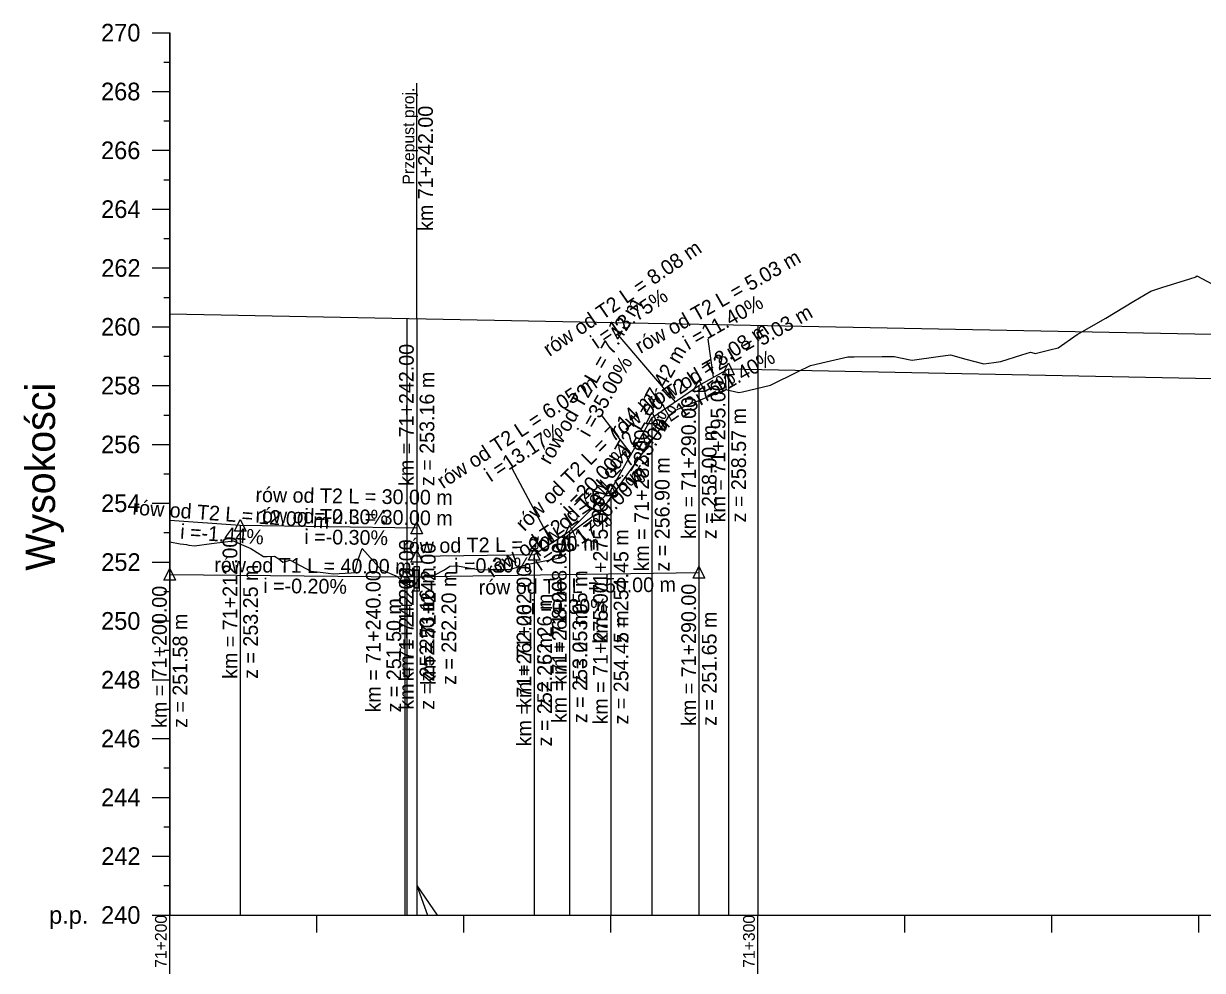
# Model space of a CAD drawing. Extents: x 6531046 to 6533341, y 5514966 to 5518007.
# Drawn here: x 6531071.2 to 6531271.6, y 5516125.3 to 5516286.3 of the extents above; entities that cross this region are included whole.
import ezdxf

# ---------------------------------------------------------------- set-up
doc = ezdxf.new("R2010")
doc.units = 0
for name, color, linetype in [('IR_default', 7, 'Continuous'), ('TOR_O-obiekty+opisy', 7, 'Continuous'), ('TOR_PROF-obiekty+opisy', 7, 'Continuous'), ('TOR_PROF-opisy pomocnicze', 7, 'Continuous'), ('TOR_PROF-rowy otwarte', 7, 'Continuous'), ('TOR_PROF-rozjazdy', 7, 'Continuous'), ('TOR_PROF-tabelka-warstwa ochronna T1', 7, 'Continuous'), ('TOR_PROF-tor projektowany', 7, 'Continuous'), ('TOR_PROF-uklad odniesienia', 7, 'Continuous'), ('TOR_PRZEK_P-tory projektowane', 7, 'Continuous'), ('TOR_RAMKI-ramka+tabelka 1', 7, 'Continuous')]:
    doc.layers.add(name, color=color, linetype=linetype)

msp = doc.modelspace()

# ---------------------------------------------------------------- linework, layer by layer
at = {"layer": 'IR_default'}
msp.add_lwpolyline([(6531096.02, 5516198.18), (6531097.78, 5516197.83), (6531098.37, 5516197.77), (6531098.88, 5516197.73), (6531099.3, 5516197.65), (6531100.26, 5516197.53), (6531103.12, 5516197.88), (6531106.88, 5516198.35), (6531107.86, 5516197.91), (6531109.81, 5516197.05), (6531111.98, 5516195.68), (6531112.61, 5516195.71), (6531113.84, 5516195.76), (6531114.56, 5516195.29), (6531115.25, 5516194.73), (6531116.48, 5516195.09), (6531117.36, 5516194.63), (6531120.01, 5516193.22), (6531122.11, 5516192.96), (6531123.84, 5516192.74), (6531126.86, 5516192.91), (6531127.51, 5516192.95), (6531128.02, 5516195), (6531128.73, 5516197.08), (6531129.63, 5516196.03), (6531131.6, 5516193.9), (6531132.06, 5516193.41), (6531134.48, 5516192.41), (6531134.68, 5516192.28), (6531135.67, 5516191.4), (6531135.94, 5516191.24), (6531136, 5516191.25), (6531136.35, 5516191.09), (6531137.27, 5516190.66), (6531137.57, 5516190.64), (6531138.6, 5516192.19), (6531139.08, 5516192.29), (6531140.42, 5516192.2), (6531141.11, 5516192.56), (6531142.75, 5516193.43), (6531143.67, 5516194.03), (6531144.96, 5516194.1), (6531145.86, 5516193.95), (6531148.81, 5516193.45), (6531150.62, 5516193.47), (6531152.32, 5516193.48), (6531153.76, 5516193.46), (6531155.37, 5516193.93), (6531156.99, 5516194.41), (6531160.12, 5516195.02), (6531162.13, 5516195.41), (6531163.13, 5516198.51), (6531163.23, 5516198.9), (6531164.41, 5516199.85), (6531164.88, 5516200.21), (6531167.79, 5516202.44), (6531169.06, 5516202.95), (6531169.63, 5516203.75), (6531174.39, 5516210.37), (6531179.14, 5516217.01), (6531180.25, 5516218.56), (6531180.91, 5516219.47), (6531181.2, 5516219.86), (6531182.05, 5516220.58), (6531183.89, 5516221.34), (6531188.65, 5516223.3), (6531190.59, 5516224.11), (6531192.81, 5516223.55), (6531193.4, 5516223.69), (6531198.16, 5516224.8), (6531198.18, 5516224.81), (6531202.91, 5516227.16), (6531204.98, 5516228.19), (6531207.66, 5516228.81), (6531211.35, 5516229.66), (6531212.42, 5516229.66), (6531217.17, 5516229.67), (6531219.24, 5516229.67), (6531221.93, 5516229.14), (6531222.29, 5516229.07), (6531226.68, 5516229.67), (6531228.81, 5516229.97), (6531231.43, 5516229.26), (6531234.48, 5516228.44), (6531236.19, 5516228.69), (6531237.34, 5516228.87), (6531240.94, 5516229.97), (6531242.39, 5516230.42), (6531242.6, 5516230.38), (6531243.19, 5516230.19), (6531245.7, 5516230.83), (6531247.09, 5516231.19), (6531250.36, 5516233.44), (6531250.45, 5516233.5), (6531253.91, 5516235.47), (6531255.21, 5516236.24), (6531259.96, 5516239.09), (6531262.85, 5516240.83), (6531264.71, 5516241.41), (6531269.47, 5516242.9), (6531270.57, 5516243.25), (6531270.71, 5516243.44), (6531274.22, 5516241.53)], dxfattribs=at)
at = {"layer": 'TOR_O-obiekty+opisy'}
msp.add_line((6531138.02, 5516236.14), (6531138.02, 5516276.14), dxfattribs=at)
at = {"layer": 'TOR_PROF-obiekty+opisy'}
for points in [[(6531138.48, 5516193.93), (6531137.56, 5516193.93), (6531137.56, 5516189.85), (6531138.48, 5516189.85)], [(6531138.4, 5516193.39), (6531137.65, 5516193.39), (6531137.65, 5516190.39), (6531138.4, 5516190.39)]]:
    msp.add_lwpolyline(points, close=True, dxfattribs=at)
for points in [[(6531138.48, 5516189.85), (6531138.48, 5516193.93), (6531137.56, 5516193.93), (6531137.56, 5516189.85), (6531138.48, 5516189.85)], [(6531138.4, 5516190.39), (6531137.65, 5516190.39), (6531137.65, 5516193.39), (6531138.4, 5516193.39), (6531138.4, 5516190.39)]]:
    msp.add_lwpolyline(points, dxfattribs=at)
at = {"layer": 'TOR_PROF-opisy pomocnicze'}
for p, q in [((6531191.02, 5516227.6), (6531191.02, 5516200.6)), ((6531186.02, 5516224.75), (6531186.02, 5516197.75)), ((6531178.02, 5516219.25), (6531178.02, 5516192.25)), ((6531171.02, 5516207), (6531171.02, 5516180)), ((6531108.02, 5516201), (6531108.02, 5516174)), ((6531138.02, 5516200.55), (6531138.02, 5516173.55)), ((6531164.02, 5516200), (6531164.02, 5516173)), ((6531138.02, 5516195.75), (6531138.02, 5516168.75)), ((6531158.02, 5516196.05), (6531158.02, 5516169.05)), ((6531096.02, 5516192.65), (6531096.02, 5516165.65)), ((6531186.02, 5516193), (6531186.02, 5516166)), ((6531136.02, 5516192.25), (6531136.02, 5516165.25))]:
    msp.add_line(p, q, dxfattribs=at)
for points in [[(6531191.02, 5516228.6), (6531192.02, 5516226.6), (6531190.02, 5516226.6)], [(6531186.02, 5516225.75), (6531187.02, 5516223.75), (6531185.02, 5516223.75)], [(6531178.02, 5516220.25), (6531179.02, 5516218.25), (6531177.02, 5516218.25)], [(6531171.02, 5516208), (6531172.02, 5516206), (6531170.02, 5516206)], [(6531108.02, 5516202), (6531109.02, 5516200), (6531107.02, 5516200)], [(6531138.02, 5516201.55), (6531139.02, 5516199.55), (6531137.02, 5516199.55)], [(6531164.02, 5516201), (6531165.02, 5516199), (6531163.02, 5516199)], [(6531138.02, 5516196.75), (6531139.02, 5516194.75), (6531137.02, 5516194.75)], [(6531158.02, 5516197.05), (6531159.02, 5516195.05), (6531157.02, 5516195.05)], [(6531096.02, 5516193.65), (6531097.02, 5516191.65), (6531095.02, 5516191.65)], [(6531136.02, 5516193.25), (6531137.02, 5516191.25), (6531135.02, 5516191.25)], [(6531186.02, 5516194), (6531187.02, 5516192), (6531185.02, 5516192)]]:
    msp.add_lwpolyline(points, close=True, dxfattribs=at)
at = {"layer": 'TOR_PROF-rowy otwarte'}
for p, q in [((6531186.02, 5516224.75), (6531191.02, 5516227.6)), ((6531191.02, 5516227.6), (6531471.02, 5516222)), ((6531178.02, 5516219.25), (6531186.02, 5516224.75)), ((6531171.02, 5516207), (6531178.02, 5516219.25)), ((6531164.02, 5516200), (6531171.02, 5516207)), ((6531096.02, 5516201.87), (6531108.02, 5516201)), ((6531108.02, 5516201), (6531138.02, 5516200.55)), ((6531158.02, 5516196.05), (6531164.02, 5516200)), ((6531138.02, 5516195.75), (6531158.02, 5516196.05)), ((6531096.02, 5516192.65), (6531136.02, 5516192.25)), ((6531136.02, 5516192.25), (6531186.02, 5516193))]:
    msp.add_line(p, q, dxfattribs=at)
for points in [[(6531096.02, 5516284.75), (6531096.02, 5516139.75), (6531096.02, 5516134.75), (6531096.02, 5516134.75)], [(6531191.02, 5516227.6), (6531191.02, 5516139.75), (6531191.02, 5516134.75), (6531191.02, 5516134.75)], [(6531186.02, 5516224.75), (6531186.02, 5516139.75), (6531186.02, 5516134.75), (6531186.02, 5516134.75)], [(6531178.02, 5516219.25), (6531178.02, 5516139.75), (6531178.02, 5516134.75), (6531178.02, 5516134.75)], [(6531171.02, 5516207), (6531171.02, 5516139.75), (6531171.02, 5516134.75), (6531171.02, 5516134.75)], [(6531096.02, 5516201.87), (6531096.02, 5516139.75), (6531096.02, 5516134.75), (6531096.02, 5516134.75)], [(6531108.02, 5516201), (6531108.02, 5516139.75), (6531108.02, 5516134.75), (6531108.02, 5516134.75)], [(6531138.02, 5516200.55), (6531138.02, 5516139.75), (6531138.02, 5516134.75), (6531138.02, 5516134.75)], [(6531164.02, 5516200), (6531164.02, 5516139.75), (6531164.02, 5516134.75), (6531164.02, 5516134.75)], [(6531138.02, 5516195.75), (6531138.02, 5516139.75), (6531141.52, 5516134.75), (6531141.52, 5516134.75)], [(6531158.02, 5516196.05), (6531158.02, 5516139.75), (6531158.02, 5516134.75), (6531158.02, 5516134.75)], [(6531096.02, 5516192.65), (6531096.02, 5516139.75), (6531096.02, 5516134.75), (6531096.02, 5516134.75)], [(6531186.02, 5516193), (6531186.02, 5516139.75), (6531186.02, 5516134.75), (6531186.02, 5516134.75)], [(6531136.02, 5516192.25), (6531136.02, 5516139.75), (6531136.02, 5516134.75), (6531136.02, 5516134.75)]]:
    msp.add_lwpolyline(points, dxfattribs=at)
at = {"layer": 'TOR_PROF-tabelka-warstwa ochronna T1'}
for points in [[(6531096.02, 5516236.95), (6531096.02, 5516139.75), (6531096.02, 5516134.75), (6531096.02, 5516134.75)], [(6531138.02, 5516236.13), (6531138.02, 5516139.75), (6531138.02, 5516134.75), (6531138.02, 5516134.75)]]:
    msp.add_lwpolyline(points, dxfattribs=at)
at = {"layer": 'TOR_PROF-tor projektowany'}
msp.add_line((6531096.02, 5516236.95), (6532296.02, 5516213.5), dxfattribs=at)
for points in [[(6531096.02, 5516236.95), (6531096.02, 5516139.75), (6531096.02, 5516134.75), (6531096.02, 5516134.75)], [(6531136.35, 5516236.16), (6531136.35, 5516139.75), (6531136.35, 5516134.75), (6531136.35, 5516134.75)], [(6531138.02, 5516236.13), (6531138.02, 5516139.75), (6531138.02, 5516134.75), (6531138.02, 5516134.75)], [(6531138.02, 5516236.13), (6531138.02, 5516139.75), (6531139.85, 5516134.75), (6531139.85, 5516134.75)], [(6531196.02, 5516235), (6531196.02, 5516139.75), (6531196.02, 5516134.75), (6531196.02, 5516134.75)]]:
    msp.add_lwpolyline(points, dxfattribs=at)
at = {"layer": 'TOR_PROF-uklad odniesienia'}
for p, q in [((6531093.02, 5516284.75), (6531096.02, 5516284.75)), ((6531096.02, 5516134.75), (6531096.02, 5516284.75)), ((6531095.02, 5516279.75), (6531096.02, 5516279.75)), ((6531093.02, 5516274.75), (6531096.02, 5516274.75)), ((6531095.02, 5516269.75), (6531096.02, 5516269.75)), ((6531093.02, 5516264.75), (6531096.02, 5516264.75)), ((6531095.02, 5516259.75), (6531096.02, 5516259.75)), ((6531093.02, 5516254.75), (6531096.02, 5516254.75)), ((6531095.02, 5516249.75), (6531096.02, 5516249.75)), ((6531093.02, 5516244.75), (6531096.02, 5516244.75)), ((6531095.02, 5516239.75), (6531096.02, 5516239.75)), ((6531093.02, 5516234.75), (6531096.02, 5516234.75)), ((6531095.02, 5516229.75), (6531096.02, 5516229.75)), ((6531093.02, 5516224.75), (6531096.02, 5516224.75)), ((6531095.02, 5516219.75), (6531096.02, 5516219.75)), ((6531093.02, 5516214.75), (6531096.02, 5516214.75)), ((6531095.02, 5516209.75), (6531096.02, 5516209.75)), ((6531093.02, 5516204.75), (6531096.02, 5516204.75)), ((6531095.02, 5516199.75), (6531096.02, 5516199.75)), ((6531093.02, 5516194.75), (6531096.02, 5516194.75)), ((6531095.02, 5516189.75), (6531096.02, 5516189.75)), ((6531093.02, 5516184.75), (6531096.02, 5516184.75)), ((6531095.02, 5516179.75), (6531096.02, 5516179.75)), ((6531093.02, 5516174.75), (6531096.02, 5516174.75)), ((6531095.02, 5516169.75), (6531096.02, 5516169.75)), ((6531093.02, 5516164.75), (6531096.02, 5516164.75)), ((6531095.02, 5516159.75), (6531096.02, 5516159.75)), ((6531093.02, 5516154.75), (6531096.02, 5516154.75)), ((6531095.02, 5516149.75), (6531096.02, 5516149.75)), ((6531093.02, 5516144.75), (6531096.02, 5516144.75)), ((6531095.02, 5516139.75), (6531096.02, 5516139.75)), ((6531093.02, 5516134.75), (6531096.02, 5516134.75)), ((6531096.02, 5516134.75), (6533096.02, 5516134.75)), ((6531096.02, 5516124.75), (6531096.02, 5516134.75)), ((6531121.02, 5516131.75), (6531121.02, 5516134.75)), ((6531146.02, 5516131.75), (6531146.02, 5516134.75)), ((6531171.02, 5516131.75), (6531171.02, 5516134.75)), ((6531196.02, 5516124.75), (6531196.02, 5516134.75)), ((6531221.02, 5516131.75), (6531221.02, 5516134.75)), ((6531246.02, 5516131.75), (6531246.02, 5516134.75)), ((6531271.02, 5516131.75), (6531271.02, 5516134.75))]:
    msp.add_line(p, q, dxfattribs=at)
at = {"layer": 'TOR_RAMKI-ramka+tabelka 1'}
for p, q in [((6531182.02, 5516222), (6531172.27, 5516233.38)), ((6531188.52, 5516226.18), (6531187.58, 5516232.65)), ((6531174.52, 5516213.13), (6531169.55, 5516219.62)), ((6531161.02, 5516198.03), (6531154.23, 5516210.66)), ((6531167.59, 5516203.57), (6531166.74, 5516205.29))]:
    msp.add_line(p, q, dxfattribs=at)

# ---------------------------------------------------------------- texts
at = {"layer": 'TOR_PROF-opisy pomocnicze'}
for s, rotation, p in [('rów od T2 L = 8.08 m', 34.5085, (6531160.61, 5516229.61)), ('rów od T2 L = 5.03 m', 29.6831, (6531176.07, 5516230.12)), ('  i =13.75%', 34.5085, (6531167.15, 5516229.86)), ('rów od T2 L = 7.42 m', 60.2551, (6531160.69, 5516211.16)), ('  i =11.40%', 29.6831, (6531182.61, 5516229.82)), ('rów od T2 L = 5.03 m', 29.6831, (6531178.08, 5516220.8)), ('rów od T2 L = 8.08 m', 34.5085, (6531172.06, 5516215.76)), ('km = 71+242.00', 90, (6531137.52, 5516207.68)), ('rów od T2 L = 7.42 m', 60.2551, (6531168.26, 5516203.18)), ('  i =11.40%', 29.6831, (6531184.62, 5516220.49)), ('  i =35.00%', 60.2551, (6531166.47, 5516214.23)), ('z = 253.16 m', 90, (6531141.02, 5516207.68)), ('  i =13.75%', 34.5085, (6531178.61, 5516216.01)), ('rów od T2 L = 6.05 m', 33.3582, (6531142.5, 5516207.13)), ('km = 71+295.00', 90, (6531190.52, 5516201.5)), ('rów od T2 L = 7.14 m', 45, (6531156.35, 5516199.85)), ('km = 71+290.00', 90, (6531185.52, 5516198.65)), ('  i =35.00%', 60.2551, (6531174.05, 5516206.25)), ('z = 258.57 m', 90, (6531194.02, 5516201.5)), ('rów od T2 L = 7.14 m', 45, (6531158.87, 5516195.55)), ('  i =13.17%', 33.3582, (6531149.05, 5516207.25)), ('km = 71+282.00', 90, (6531177.52, 5516193.15)), ('z = 258.00 m', 90, (6531189.02, 5516198.65)), ('  i =20.00%', 45, (6531162.74, 5516201.29)), ('z = 256.90 m', 90, (6531181.02, 5516193.15)), ('rów od T2 L = 6.05 m', 33.3582, (6531150.94, 5516191.99)), ('  i =20.00%', 45, (6531165.25, 5516196.99)), ('rów od T2 L = 30.00 m', 359.1406, (6531110.59, 5516204.96)), ('rów od T2 L = 12.00 m', 355.8691, (6531089.65, 5516202.83)), ('km = 71+275.00', 90, (6531170.52, 5516180.9)), ('rów od T2 L = 30.00 m', 359.1406, (6531110.59, 5516201.46)), ('  i =-0.30%', 359.1406, (6531117.05, 5516201.36)), ('  i =13.17%', 33.3582, (6531157.49, 5516192.11)), ('  i =-1.44%', 355.8691, (6531095.89, 5516198.87)), ('  i =-0.30%', 359.1406, (6531117.05, 5516197.86)), ('km = 71+212.00', 90, (6531107.52, 5516174.9)), ('km = 71+242.00', 90, (6531137.52, 5516174.45)), ('rów od T2 L = 20.00 m', 0.8594, (6531135.58, 5516196.21)), ('z = 254.45 m', 90, (6531174.02, 5516180.9)), ('km = 71+242.00', 90, (6531141.24, 5516173.86)), ('km = 71+268.00', 90, (6531163.52, 5516173.9)), ('rów od T1 L = 40.00 m', 359.4271, (6531103.59, 5516193.07)), ('  i =0.30%', 0.8594, (6531142.56, 5516192.82)), ('z = 253.25 m', 90, (6531111.02, 5516174.9)), ('km = 71+240.00', 90, (6531131.88, 5516169.19)), ('km = 71+242.00', 90, (6531137.52, 5516169.65)), ('z = 253.16 m', 90, (6531141.02, 5516174.45)), ('z = 252.20 m', 90, (6531144.74, 5516173.86)), ('km = 71+262.00', 90, (6531157.52, 5516169.95)), ('z = 253.05 m', 90, (6531167.02, 5516173.9)), ('km = 71+200.00', 90, (6531095.52, 5516166.55)), ('  i =-0.20%', 359.4271, (6531110.07, 5516189.51)), ('rów od T1 L = 50.00 m', 0.8594, (6531148.58, 5516189.22)), ('km = 71+268.00', 90, (6531163.52, 5516167.37)), ('km = 71+275.00', 90, (6531170.52, 5516167.14)), ('km = 71+290.00', 90, (6531185.52, 5516166.9)), ('z = 251.50 m', 90, (6531135.38, 5516169.19)), ('z = 252.20 m', 90, (6531141.02, 5516169.65)), ('  i =0.30%', 0.8594, (6531155.56, 5516185.82)), ('z = 252.26 m', 90, (6531161.02, 5516169.95)), ('km = 71+262.00', 90, (6531157.52, 5516163.42)), ('z = 253.05 m', 90, (6531167.02, 5516167.37)), ('z = 254.45 m', 90, (6531174.02, 5516167.14)), ('z = 251.58 m', 90, (6531099.02, 5516166.55)), ('z = 251.65 m', 90, (6531189.02, 5516166.9)), ('z = 252.26 m', 90, (6531161.02, 5516163.42))]:
    msp.add_text(s, height=2.5, rotation=rotation, dxfattribs=at).set_placement(p)
at = {"layer": 'TOR_PROF-rozjazdy'}
msp.add_text('km 71+242.00', height=2.5, rotation=90, dxfattribs=at).set_placement((6531140.77, 5516251.04))
at = {"layer": 'TOR_PROF-uklad odniesienia'}
for s, height, p in [('270', 3, (6531084.35, 5516283.25)), ('268', 3, (6531084.34, 5516273.25)), ('266', 3, (6531084.34, 5516263.25)), ('264', 3, (6531084.36, 5516253.25)), ('262', 3, (6531084.38, 5516243.25)), ('260', 3, (6531084.35, 5516233.25)), ('258', 3, (6531084.34, 5516223.25)), ('256', 3, (6531084.34, 5516213.25)), ('254', 3, (6531084.36, 5516203.25)), ('252', 3, (6531084.38, 5516193.25)), ('250', 3, (6531084.35, 5516183.25)), ('248', 3, (6531084.34, 5516173.25)), ('246', 3, (6531084.34, 5516163.25)), ('244', 3, (6531084.36, 5516153.25)), ('242', 3, (6531084.38, 5516143.25)), ('240', 3, (6531084.35, 5516133.25)), ('p.p.', 3, (6531075.51, 5516133.25)), ('-', 0.0001, (6531096.02, 5516134.75))]:
    msp.add_text(s, height=height, dxfattribs=at).set_placement(p)
for s, height, p in [('Wysokości', 5, (6531076.52, 5516193.28)), ('71+200', 2, (6531095.52, 5516125.77)), ('71+300', 2, (6531195.52, 5516125.77))]:
    msp.add_text(s, height=height, rotation=90, dxfattribs=at).set_placement(p)
at = {"layer": 'TOR_PRZEK_P-tory projektowane'}
msp.add_text('Przepust proj.', height=2, rotation=90, dxfattribs=at).set_placement((6531137.62, 5516258.91))

doc.saveas('drawing.dxf')
